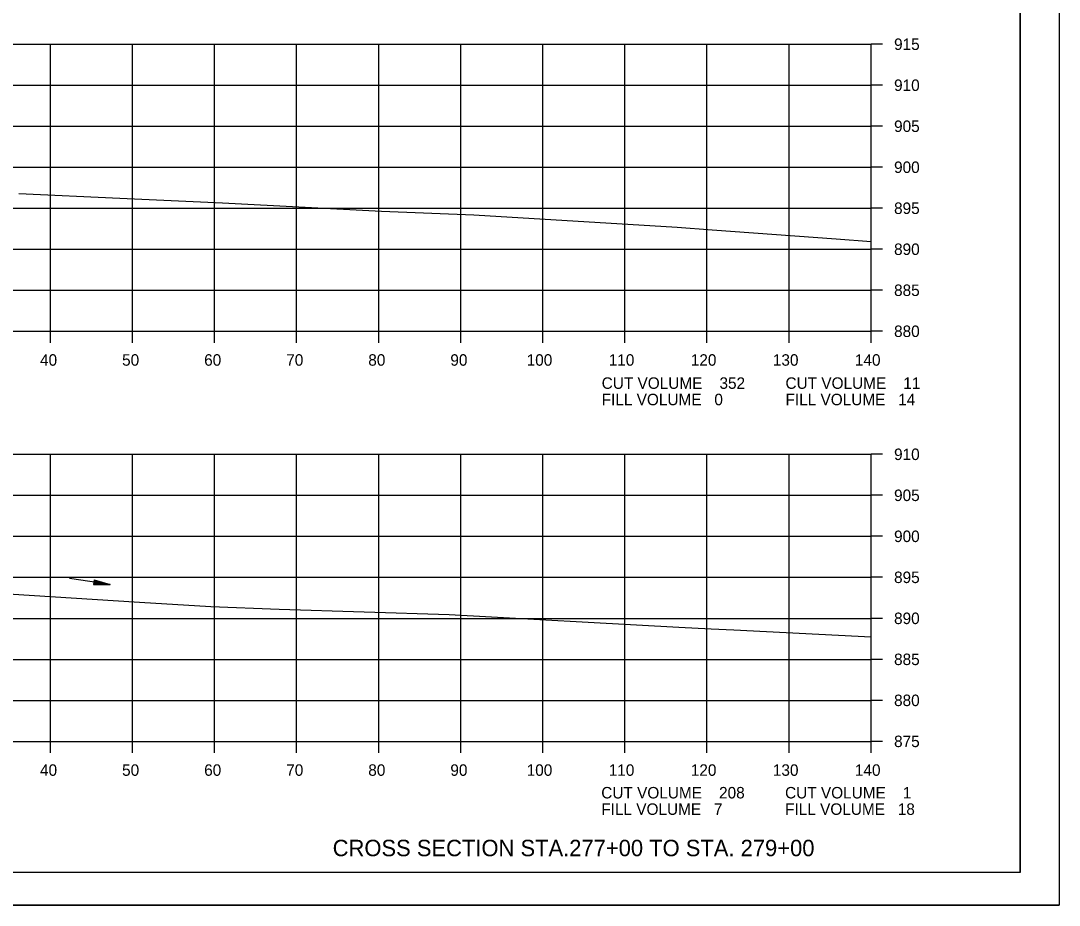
# Model space of a CAD drawing. Extents: x 1486524 to 1499135, y 326561 to 337924.
# Drawn here: x 1489019.3 to 1489145.8, y 331285.9 to 331393.8 of the extents above; entities that cross this region are included whole.
import ezdxf

# ---------------------------------------------------------------- set-up
doc = ezdxf.new("R2010")
doc.units = 0
for name, color, linetype in [('E_Const Align', 7, 'Continuous'), ('E_Const Align Station', 7, 'Continuous'), ('E_Ownership Information', 7, 'Continuous'), ('E_Property Line', 7, 'Continuous'), ('E_Proposed ROW Fig Annot', 7, 'Continuous'), ('E_Quarter Calls', 7, 'Continuous'), ('E_Tract Number', 7, 'Continuous'), ('R_Water Annot', 7, 'Continuous')]:
    doc.layers.add(name, color=color, linetype=linetype)

msp = doc.modelspace()

# ---------------------------------------------------------------- linework, layer by layer
at = {"layer": 'E_Const Align'}
for p, q in [((1489122.89, 331355.92), (1489122.89, 331390.92)), ((1489124.29, 331390.92), (1489122.89, 331390.92)), ((1489124.29, 331385.92), (1489122.89, 331385.92)), ((1489124.29, 331380.92), (1489122.89, 331380.92)), ((1489124.29, 331375.92), (1489122.89, 331375.92)), ((1489124.29, 331370.92), (1489122.89, 331370.92)), ((1489124.29, 331365.92), (1489122.89, 331365.92)), ((1489124.29, 331360.92), (1489122.89, 331360.92)), ((1488842.89, 331355.92), (1489122.89, 331355.92)), ((1489022.89, 331354.52), (1489022.89, 331355.92)), ((1489032.89, 331354.52), (1489032.89, 331355.92)), ((1489042.89, 331354.52), (1489042.89, 331355.92)), ((1489052.89, 331354.52), (1489052.89, 331355.92)), ((1489062.89, 331354.52), (1489062.89, 331355.92)), ((1489072.89, 331354.52), (1489072.89, 331355.92)), ((1489082.89, 331354.52), (1489082.89, 331355.92)), ((1489092.89, 331354.52), (1489092.89, 331355.92)), ((1489102.89, 331354.52), (1489102.89, 331355.92)), ((1489112.89, 331354.52), (1489112.89, 331355.92)), ((1489122.89, 331354.52), (1489122.89, 331355.92)), ((1489124.29, 331355.92), (1489122.89, 331355.92)), ((1489122.89, 331305.92), (1489122.89, 331340.92)), ((1489124.29, 331340.92), (1489122.89, 331340.92)), ((1489124.29, 331335.92), (1489122.89, 331335.92)), ((1489124.29, 331330.92), (1489122.89, 331330.92)), ((1489124.29, 331325.92), (1489122.89, 331325.92)), ((1489124.29, 331320.92), (1489122.89, 331320.92)), ((1489124.29, 331315.92), (1489122.89, 331315.92)), ((1489124.29, 331310.92), (1489122.89, 331310.92)), ((1488842.89, 331305.92), (1489122.89, 331305.92)), ((1489022.89, 331304.52), (1489022.89, 331305.92)), ((1489032.89, 331304.52), (1489032.89, 331305.92)), ((1489042.89, 331304.52), (1489042.89, 331305.92)), ((1489052.89, 331304.52), (1489052.89, 331305.92)), ((1489062.89, 331304.52), (1489062.89, 331305.92)), ((1489072.89, 331304.52), (1489072.89, 331305.92)), ((1489082.89, 331304.52), (1489082.89, 331305.92)), ((1489092.89, 331304.52), (1489092.89, 331305.92)), ((1489102.89, 331304.52), (1489102.89, 331305.92)), ((1489112.89, 331304.52), (1489112.89, 331305.92)), ((1489122.89, 331304.52), (1489122.89, 331305.92)), ((1489124.29, 331305.92), (1489122.89, 331305.92))]:
    msp.add_line(p, q, dxfattribs=at)
at = {"layer": 'E_Ownership Information'}
for p, q in [((1488842.89, 331390.92), (1489122.89, 331390.92)), ((1489022.89, 331355.92), (1489022.89, 331390.92)), ((1489032.89, 331355.92), (1489032.89, 331390.92)), ((1489042.89, 331355.92), (1489042.89, 331390.92)), ((1489052.89, 331355.92), (1489052.89, 331390.92)), ((1489062.89, 331355.92), (1489062.89, 331390.92)), ((1489072.89, 331355.92), (1489072.89, 331390.92)), ((1489082.89, 331355.92), (1489082.89, 331390.92)), ((1489092.89, 331355.92), (1489092.89, 331390.92)), ((1489102.89, 331355.92), (1489102.89, 331390.92)), ((1489112.89, 331355.92), (1489112.89, 331390.92)), ((1489122.89, 331355.92), (1489122.89, 331390.92)), ((1488842.89, 331385.92), (1489122.89, 331385.92)), ((1488842.89, 331380.92), (1489122.89, 331380.92)), ((1488842.89, 331375.92), (1489122.89, 331375.92)), ((1488842.89, 331370.92), (1489122.89, 331370.92)), ((1488842.89, 331365.92), (1489122.89, 331365.92)), ((1488842.89, 331360.92), (1489122.89, 331360.92)), ((1488842.89, 331355.92), (1489122.89, 331355.92)), ((1488842.89, 331340.92), (1489122.89, 331340.92)), ((1489022.89, 331305.92), (1489022.89, 331340.92)), ((1489032.89, 331305.92), (1489032.89, 331340.92)), ((1489042.89, 331305.92), (1489042.89, 331340.92)), ((1489052.89, 331305.92), (1489052.89, 331340.92)), ((1489062.89, 331305.92), (1489062.89, 331340.92)), ((1489072.89, 331305.92), (1489072.89, 331340.92)), ((1489082.89, 331305.92), (1489082.89, 331340.92)), ((1489092.89, 331305.92), (1489092.89, 331340.92)), ((1489102.89, 331305.92), (1489102.89, 331340.92)), ((1489112.89, 331305.92), (1489112.89, 331340.92)), ((1489122.89, 331305.92), (1489122.89, 331340.92)), ((1488842.89, 331335.92), (1489122.89, 331335.92)), ((1488842.89, 331330.92), (1489122.89, 331330.92)), ((1488842.89, 331325.92), (1489122.89, 331325.92)), ((1488842.89, 331320.92), (1489122.89, 331320.92)), ((1488842.89, 331315.92), (1489122.89, 331315.92)), ((1488842.89, 331310.92), (1489122.89, 331310.92)), ((1488842.89, 331305.92), (1489122.89, 331305.92))]:
    msp.add_line(p, q, dxfattribs=at)
at = {"layer": 'E_Property Line'}
for q in [(1489141.07, 331495.38), (1488824.89, 331289.92)]:
    msp.add_line((1489141.07, 331289.92), q, dxfattribs=at)
at = {"layer": 'E_Proposed ROW Fig Annot'}
for p, q in [((1489028.23, 331325.63), (1489028.15, 331325.04)), ((1489028.23, 331325.63), (1489028.15, 331325.04)), ((1489028.15, 331325.04), (1489030.17, 331325.05)), ((1489028.15, 331325.04), (1489030.17, 331325.05)), ((1489028.16, 331325.14), (1489029.5, 331325.15)), ((1489028.16, 331325.14), (1489029.5, 331325.15)), ((1489028.16, 331325.08), (1489029.84, 331325.1)), ((1489028.16, 331325.08), (1489029.84, 331325.1)), ((1489028.17, 331325.18), (1489029.17, 331325.19)), ((1489028.17, 331325.18), (1489029.17, 331325.19)), ((1489028.18, 331325.24), (1489028.84, 331325.24)), ((1489028.18, 331325.24), (1489028.84, 331325.24)), ((1489028.19, 331325.29), (1489028.5, 331325.29)), ((1489028.19, 331325.29), (1489028.5, 331325.29)), ((1489028.2, 331325.38), (1489028.5, 331325.29)), ((1489028.2, 331325.38), (1489028.5, 331325.29)), ((1489028.21, 331325.48), (1489029.17, 331325.19)), ((1489028.21, 331325.48), (1489029.17, 331325.19)), ((1489028.21, 331325.43), (1489028.84, 331325.24)), ((1489028.21, 331325.43), (1489028.84, 331325.24)), ((1489028.22, 331325.53), (1489029.5, 331325.15)), ((1489028.22, 331325.53), (1489029.5, 331325.15)), ((1489028.23, 331325.63), (1489030.17, 331325.05)), ((1489028.23, 331325.63), (1489030.17, 331325.05)), ((1489028.23, 331325.58), (1489029.84, 331325.1)), ((1489028.23, 331325.58), (1489029.84, 331325.1))]:
    msp.add_line(p, q, dxfattribs=at)
at = {"layer": 'E_Quarter Calls'}
msp.add_line((1488812.48, 331285.94), (1489145.82, 331285.94), dxfattribs=at)
for points in [[(1488812.48, 331499.28), (1489145.82, 331499.28), (1489145.82, 331285.94), (1488812.48, 331285.94)], [(1489058.81, 331495.38), (1489058.81, 331485.5), (1489094.54, 331485.5), (1489094.54, 331482.58), (1489117.74, 331482.58), (1489117.74, 331458.25), (1489141.07, 331458.25), (1489141.07, 331289.92), (1488824.89, 331289.92), (1488824.89, 331495.38)]]:
    msp.add_lwpolyline(points, close=True, dxfattribs=at)
at = {"layer": 'E_Tract Number'}
for points in [[(1489019.04, 331372.7), (1489031.33, 331372.15), (1489043.87, 331371.58), (1489063.25, 331370.58), (1489074.49, 331370.13), (1489099.28, 331368.6), (1489103.53, 331368.27), (1489118.65, 331367.19), (1489122.89, 331366.87)], [(1489015.12, 331324.05), (1489033.76, 331322.89), (1489042.45, 331322.37), (1489050.75, 331322.04), (1489071.47, 331321.38), (1489099.47, 331319.86), (1489103.4, 331319.65), (1489106.18, 331319.51), (1489122.89, 331318.66)]]:
    msp.add_lwpolyline(points, dxfattribs=at)
at = {"layer": 'R_Water Annot'}
msp.add_line((1489030.17, 331325.05), (1489025.22, 331325.76), dxfattribs=at)

# ---------------------------------------------------------------- texts
at = {"layer": 'E_Const Align Station'}
for s, p in [('915', (1489125.69, 331390.22)), ('910', (1489125.69, 331385.22)), ('905', (1489125.69, 331380.22)), ('900', (1489125.69, 331375.22)), ('895', (1489125.69, 331370.22)), ('890', (1489125.69, 331365.22)), ('885', (1489125.69, 331360.22)), ('880', (1489125.69, 331355.22)), ('40', (1489021.62, 331351.72)), ('50', (1489031.62, 331351.72)), ('60', (1489041.62, 331351.72)), ('70', (1489051.62, 331351.72)), ('80', (1489061.62, 331351.72)), ('90', (1489071.62, 331351.72)), ('100', (1489080.92, 331351.72)), ('110', (1489090.92, 331351.72)), ('120', (1489100.92, 331351.72)), ('130', (1489110.92, 331351.72)), ('140', (1489120.92, 331351.72)), ('CUT VOLUME    352', (1489090.06, 331348.9)), ('CUT VOLUME    11', (1489112.46, 331348.9)), ('FILL VOLUME   0', (1489090.06, 331346.9)), ('FILL VOLUME   14', (1489112.46, 331346.9)), ('910', (1489125.69, 331340.22)), ('905', (1489125.69, 331335.22)), ('900', (1489125.69, 331330.22)), ('895', (1489125.69, 331325.22)), ('890', (1489125.69, 331320.22)), ('885', (1489125.69, 331315.22)), ('880', (1489125.69, 331310.22)), ('875', (1489125.69, 331305.22)), ('40', (1489021.62, 331301.72)), ('50', (1489031.62, 331301.72)), ('60', (1489041.62, 331301.72)), ('70', (1489051.62, 331301.72)), ('80', (1489061.62, 331301.72)), ('90', (1489071.62, 331301.72)), ('100', (1489080.92, 331301.72)), ('110', (1489090.92, 331301.72)), ('120', (1489100.92, 331301.72)), ('130', (1489110.92, 331301.72)), ('140', (1489120.92, 331301.72)), ('CUT VOLUME    208', (1489090.01, 331298.96)), ('CUT VOLUME    1', (1489112.41, 331298.96)), ('FILL VOLUME   7', (1489090.01, 331296.96)), ('FILL VOLUME   18', (1489112.41, 331296.96))]:
    msp.add_text(s, height=1.4, dxfattribs=at).set_placement(p)
at = {"layer": 'E_Proposed ROW Fig Annot'}
msp.add_text('CROSS SECTION STA.277+00 TO STA. 279+00', height=2, dxfattribs=at).set_placement((1489057.28, 331291.92))

doc.saveas('drawing.dxf')
